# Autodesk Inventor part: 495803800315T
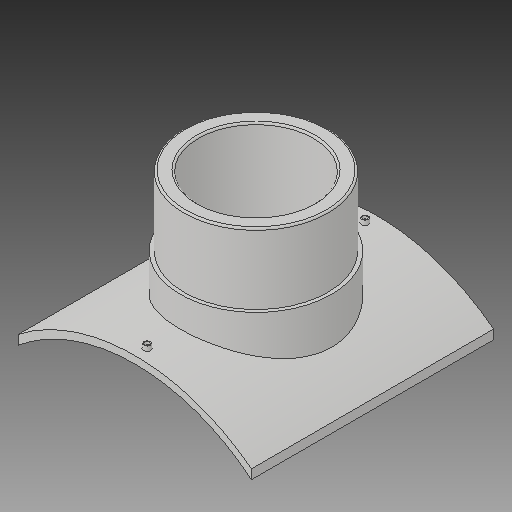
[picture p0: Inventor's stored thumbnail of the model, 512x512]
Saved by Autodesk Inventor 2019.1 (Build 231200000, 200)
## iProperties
Created: 2017-10
Part Number: 495803800315T
Material: Generic
Description: PLASSON BRANCH SADDLE  800x315
Document SubType Name: Modeling
Designer: KIM
Mass: 2754.05 g
Surface Area: 3037.44 cm^2
Volume: 2754.05 cm^3
Density: 1 g/cm^3
Appearance: Default
Author: KIM
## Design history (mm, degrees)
derived "495803.ipt"
feature "Solid1::495803.ipt"
tag "TaggingFeature1"
body "Solid1"
other parameters: "d1" = 16, "d4" = 0, "d12" = 425.6, "d13" = 14, "d14" = 238.5, "d16" = 5 deg, "d18" = 4, "d19" = 14, "d20" = 0, "d21" = 3, "d22" = 0, "d23" = 636, "d24" = 330.75, "d25" = 16, "d26" = 252, "d28" = 0, "d29" = 9.6, "d31" = 0, "d33" = 0, "d34" = 8, "d36" = 315, "d37" = 154, "d38" = 0, "d39" = 4, "d_1" = 315, "x_" = 16, "D_" = 16
